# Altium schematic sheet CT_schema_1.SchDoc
size 536 x 483 mm
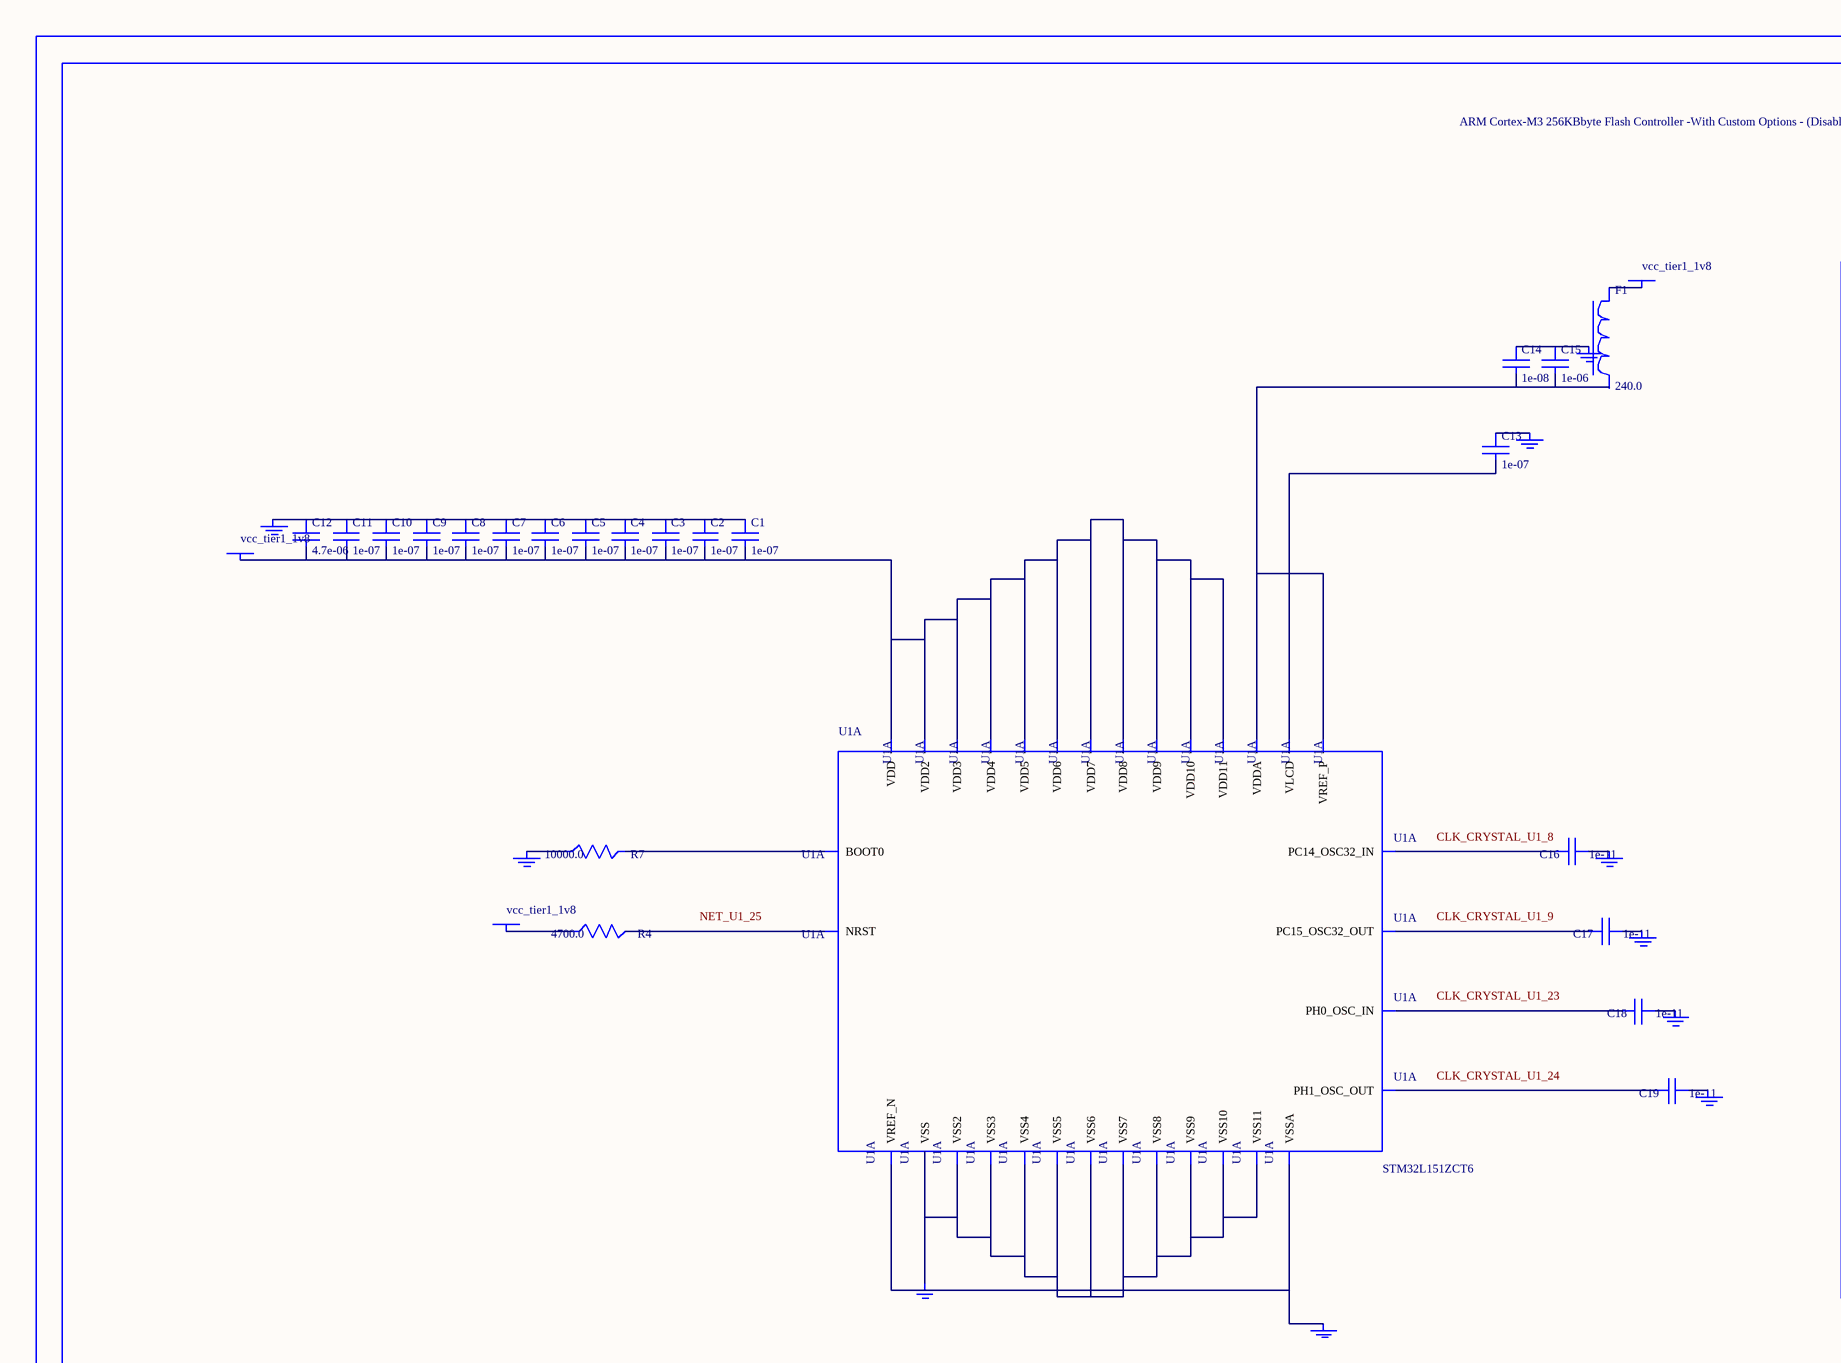
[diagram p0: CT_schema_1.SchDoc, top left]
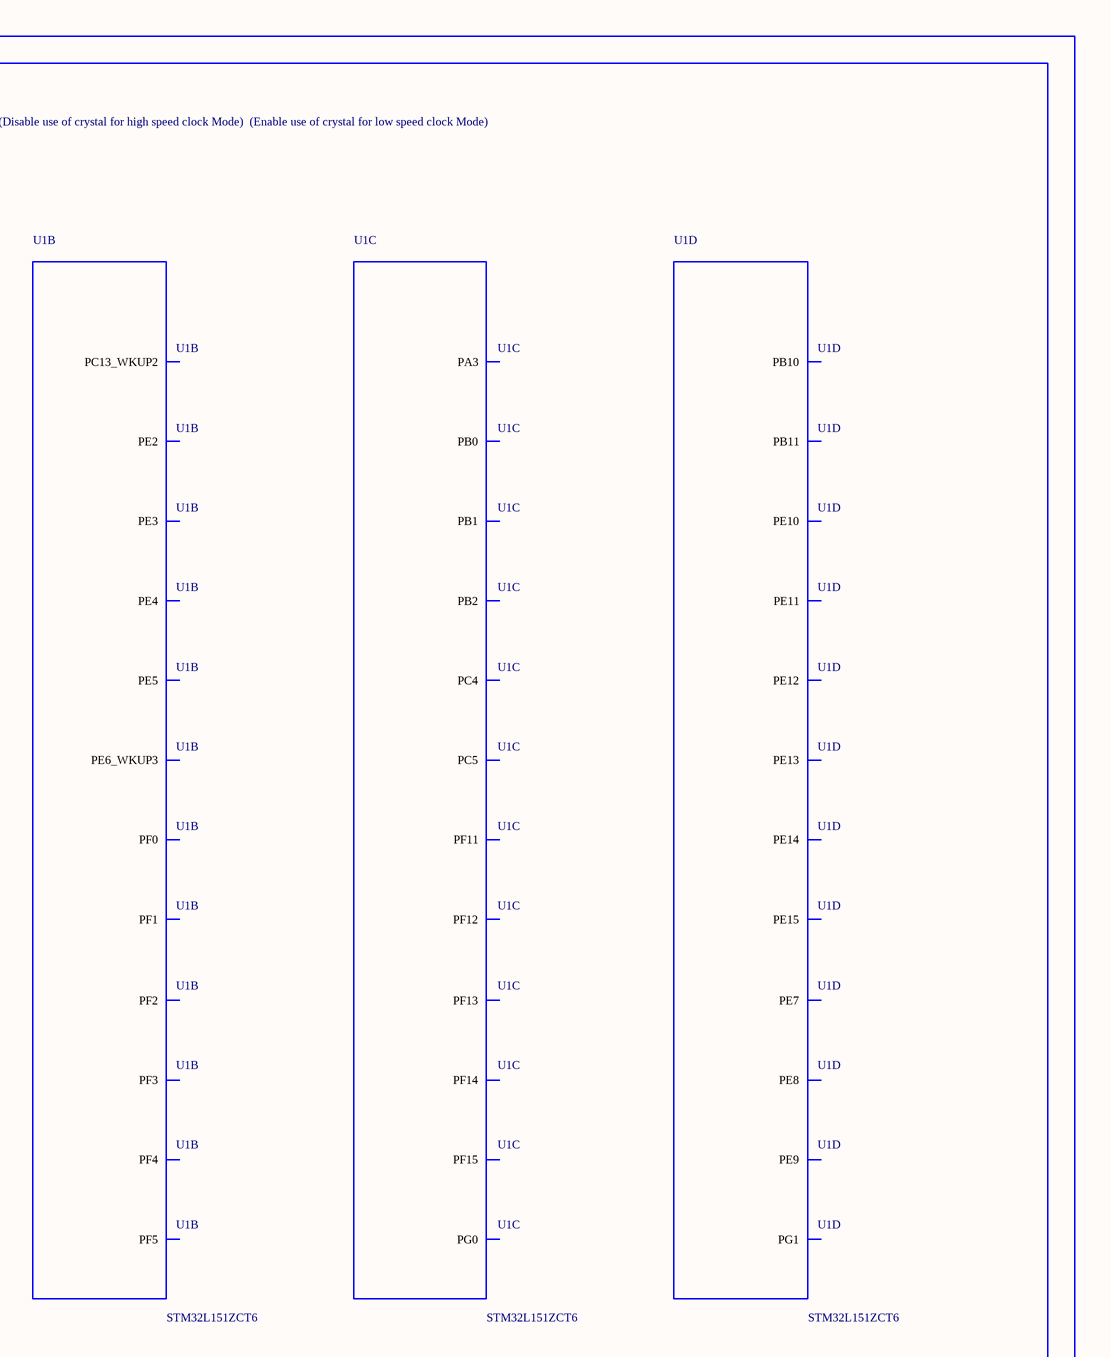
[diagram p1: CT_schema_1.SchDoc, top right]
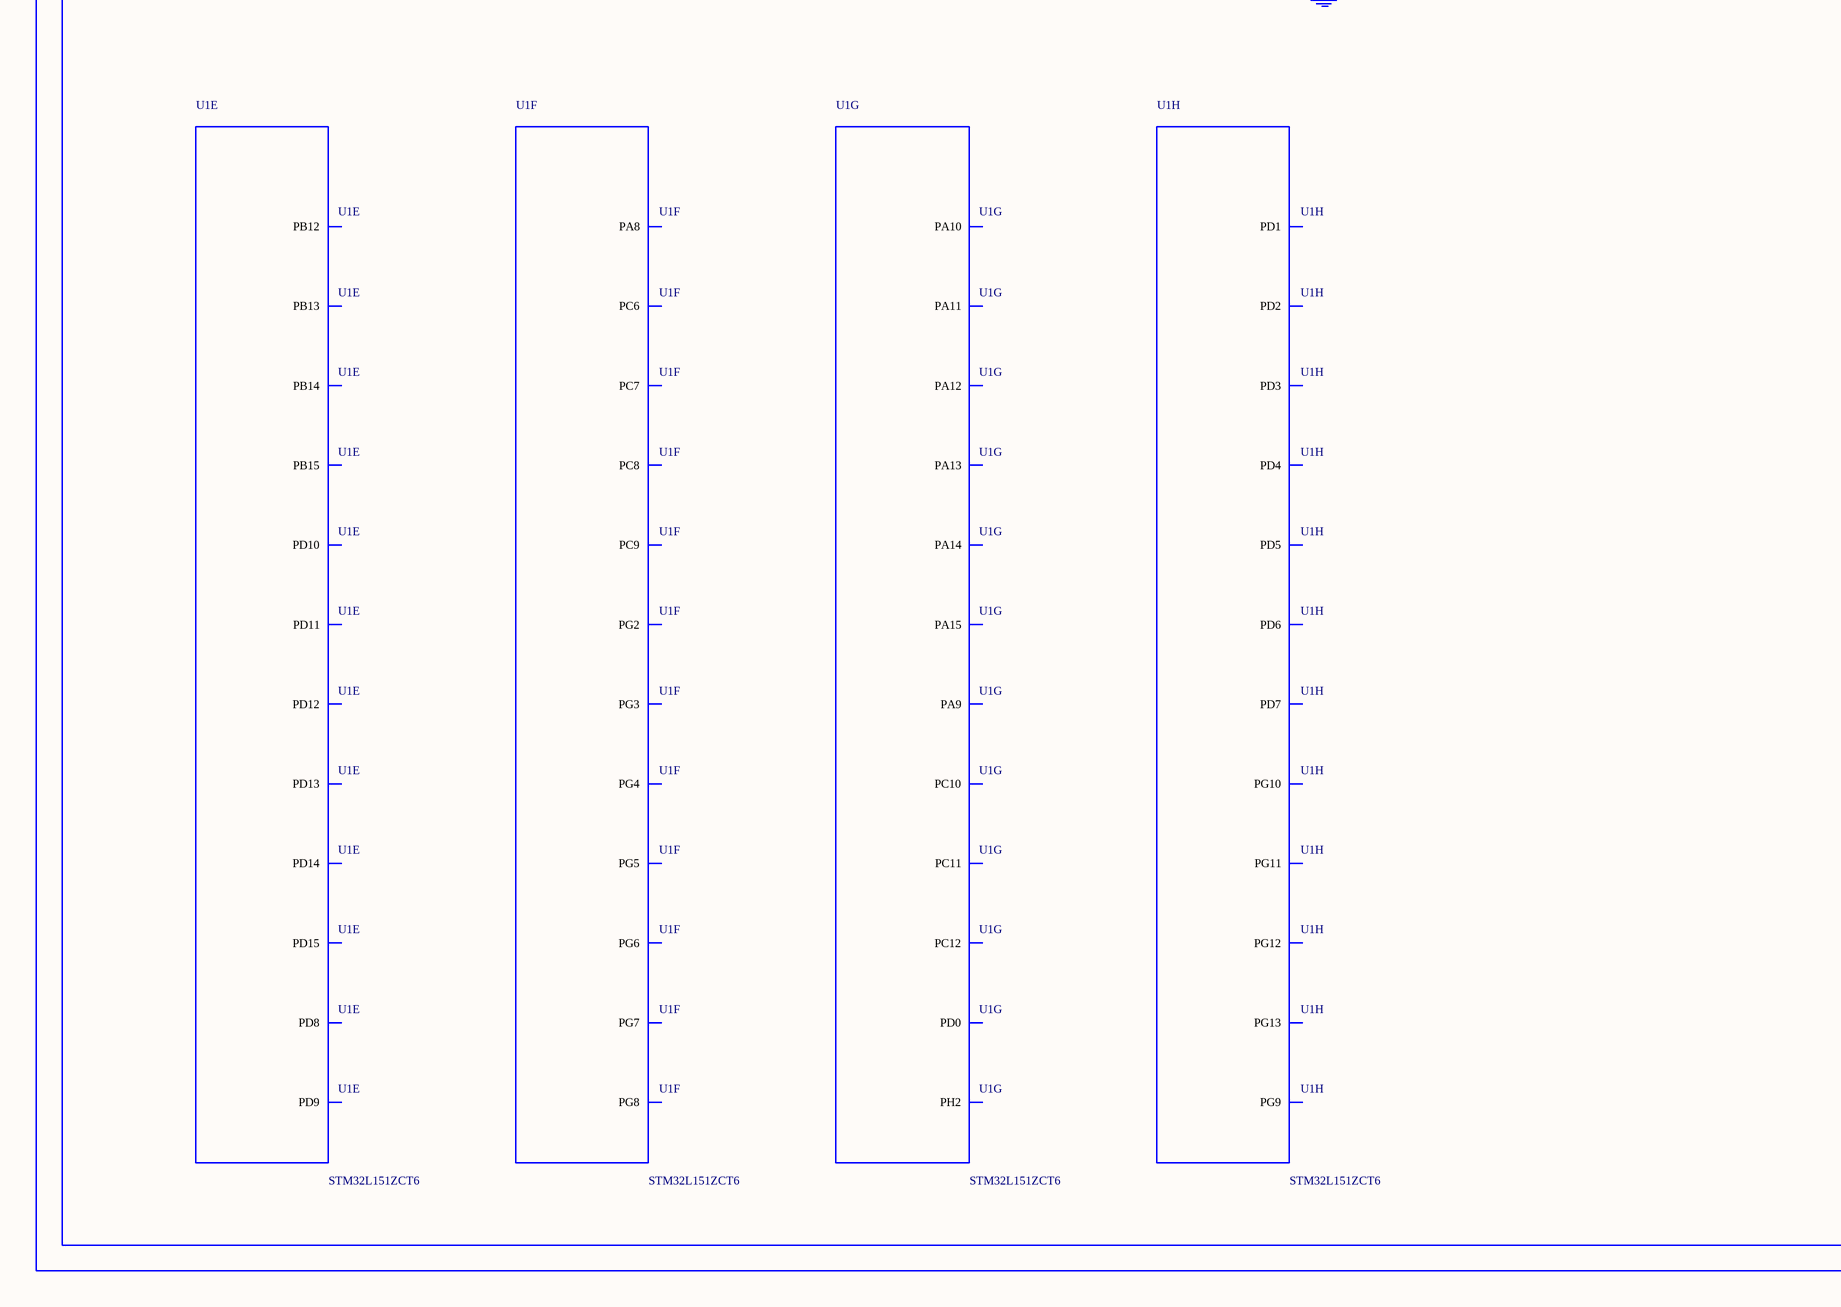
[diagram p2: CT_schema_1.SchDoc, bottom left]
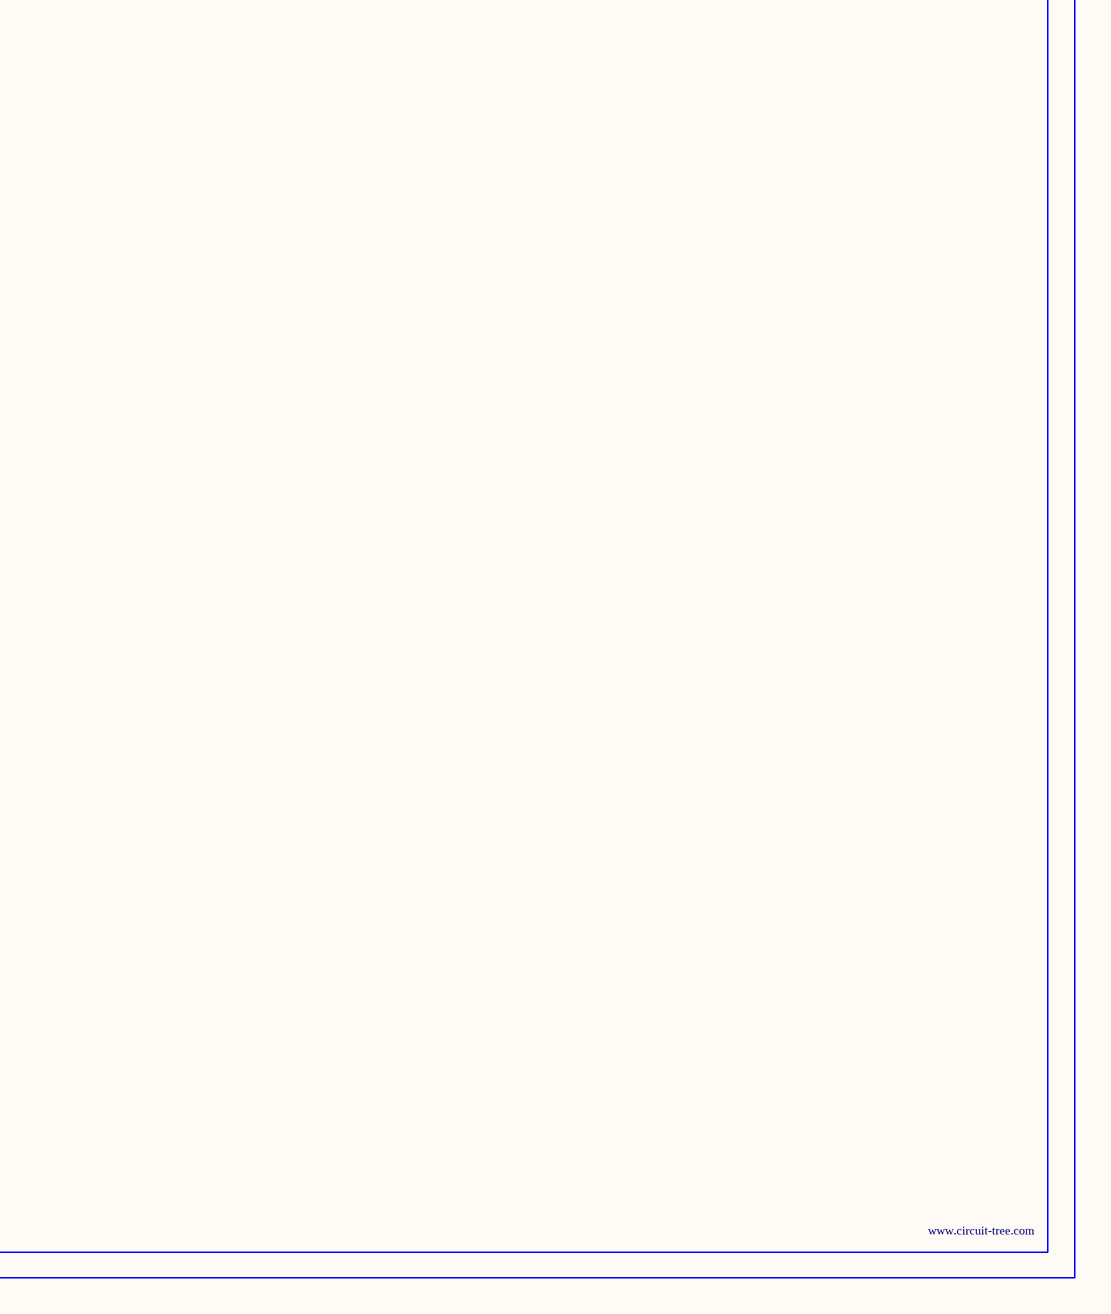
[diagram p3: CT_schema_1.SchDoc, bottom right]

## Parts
BORDER0  (no value)
C1  1e-07  [C0603]
C2  1e-07  [C0603]
C3  1e-07  [C0603]
C4  1e-07  [C0603]
C5  1e-07  [C0603]
C6  1e-07  [C0603]
C7  1e-07  [C0603]
C8  1e-07  [C0603]
C9  1e-07  [C0603]
C10  1e-07  [C0603]
C11  1e-07  [C0603]
C12  4.7e-06  [C0603]
C13  1e-07  [C0603]
C14  1e-08  [C0603]
C15  1e-06  [C0603]
C16  1e-11  [C0402]
C17  1e-11  [C0402]
C18  1e-11  [C0402]
C19  1e-11  [C0402]
F1  240.0  [L0603]
GND_INSTANCE_0_0  (no value)
GND_INSTANCE_0_1  (no value)
GND_INSTANCE_0_2  (no value)
GND_INSTANCE_0_3  (no value)
GND_INSTANCE_0_4  (no value)
GND_INSTANCE_0_5  (no value)
GND_INSTANCE_0_6  (no value)
GND_INSTANCE_0_7  (no value)
GND_INSTANCE_0_8  (no value)
GND_INSTANCE_0_9  (no value)
POWER_INSTANCE_0_0  vcc_tier1_1v8
POWER_INSTANCE_0_1  vcc_tier1_1v8
POWER_INSTANCE_0_2  vcc_tier1_1v8
R4  4700.0  [R0603]
R7  10000.0  [R0603]
U1  STM32L151ZCT6  [LQFP144]  (parts A,B,C,D,E,F,G,H of 11)

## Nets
NetC1_1: C1.1 C2.1 C3.1 C4.1 C5.1 C6.1 C7.1 C8.1 C9.1 C10.1 C11.1 C12.1 GND_INSTANCE_0_3.0(GND)
NetC1_2: C1.2 C2.2 C3.2 C4.2 C5.2 C6.2 C7.2 C8.2 C9.2 C10.2 C11.2 C12.2 POWER_INSTANCE_0_0.0(PWR) U1.17(VDD) U1.39(VDD2) U1.52(VDD3) U1.62(VDD4) U1.72(VDD5) U1.84(VDD6) U1.95(VDD7) U1.108(VDD8) U1.121(VDD9) U1.131(VDD10) U1.144(VDD11)
NetC13_1: C13.1 GND_INSTANCE_0_0.0(GND)
NetC13_2: C13.2 U1.6(VLCD)
NetC14_1: C14.1 C15.1 GND_INSTANCE_0_7.0(GND)
NetC14_2: C14.2 C15.2 U1.32(VREF_P) U1.33(VDDA)
NetC16_1: C16.1 GND_INSTANCE_0_1.0(GND)
NetC16_2: C16.2 U1.8(PC14_OSC32_IN)
NetC17_1: C17.1 GND_INSTANCE_0_2.0(GND)
NetC17_2: C17.2 U1.9(PC15_OSC32_OUT)
NetC18_1: C18.1 GND_INSTANCE_0_4.0(GND)
NetC18_2: C18.2 U1.23(PH0_OSC_IN)
NetC19_1: C19.1 GND_INSTANCE_0_5.0(GND)
NetC19_2: C19.2 U1.24(PH1_OSC_OUT)
NetF1_1: F1.1 POWER_INSTANCE_0_1.0(PWR)
NetGND_INSTANCE_0_6_0: GND_INSTANCE_0_6.0(GND) U1.30(VSSA) U1.31(VREF_N)
NetGND_INSTANCE_0_8_0: GND_INSTANCE_0_8.0(GND) R7.1
NetGND_INSTANCE_0_9_0: GND_INSTANCE_0_9.0(GND) U1.16(VSS) U1.38(VSS2) U1.51(VSS3) U1.61(VSS4) U1.71(VSS5) U1.83(VSS6) U1.94(VSS7) U1.107(VSS8) U1.120(VSS9) U1.130(VSS10) U1.143(VSS11)
NetPOWER_INSTANCE_0_2_0: POWER_INSTANCE_0_2.0(PWR) R4.1
NetR4_2: R4.2 U1.25(NRST)
NetR7_2: R7.2 U1.138(BOOT0)

Not connected (* = marked no-connect by the designer): F1 2; U1 1(PE2) 2(PE3) 3(PE4) 4(PE5) 5(PE6_WKUP3) 7(PC13_WKUP2) 10(PF0) 11(PF1) 12(PF2) 13(PF3) 14(PF4) 15(PF5) 37(PA3) 44(PC4) 45(PC5) 46(PB0) 47(PB1) 48(PB2) 49(PF11) 50(PF12) 53(PF13) 54(PF14) 55(PF15) 56(PG0) 57(PG1) 58(PE7) 59(PE8) 60(PE9) 63(PE10) 64(PE11) 65(PE12) 66(PE13) 67(PE14) 68(PE15) 69(PB10) 70(PB11) 73(PB12) 74(PB13) 75(PB14) 76(PB15) 77(PD8) 78(PD9) 79(PD10) 80(PD11) 81(PD12) 82(PD13) 85(PD14) 86(PD15) 87(PG2) 88(PG3) 89(PG4) 90(PG5) 91(PG6) 92(PG7) 93(PG8) 96(PC6) 97(PC7) 98(PC8) 99(PC9) 100(PA8) 101(PA9) 102(PA10) 103(PA11) 104(PA12) 105(PA13) 106(PH2) 109(PA14) 110(PA15) 111(PC10) 112(PC11) 113(PC12) 114(PD0) 115(PD1) 116(PD2) 117(PD3) 118(PD4) 119(PD5) 122(PD6) 123(PD7) 124(PG9) 125(PG10) 126(PG11) 127(PG12) 128(PG13)

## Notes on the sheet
- Labels drawn without touching a wire or pin: CLK_CRYSTAL_U1_8, CLK_CRYSTAL_U1_9, CLK_CRYSTAL_U1_23, CLK_CRYSTAL_U1_24, NET_U1_25

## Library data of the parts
BORDER0 = BORDER_PAGE0
C1-C11 C13 = 06035C104K4Z2A
C12 = GRM188R6YA475KE15D
C14 = 06035C103K4Z2A
C15 = C0603C105K3RACTU
C16-C19 = C0402C100K3GACTU
F1 = Z0603C241ASMST
GND_INSTANCE_0_0-GND_INSTANCE_0_9 = GND
POWER_INSTANCE_0_0-POWER_INSTANCE_0_2 = PWR
R4 = RC0603JR-074K7L
R7 = RC0603JR-0710KL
